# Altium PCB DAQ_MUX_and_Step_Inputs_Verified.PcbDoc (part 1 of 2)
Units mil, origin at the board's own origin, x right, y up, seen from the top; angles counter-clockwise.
Board outline 3200 x 1700 mil, 4 copper layers (Top Layer, InternalPlane1, InternalPlane2, Bottom Layer), stack 61.7 mil thick; 78 components, 60 nets, 284 pads, 100 vias.
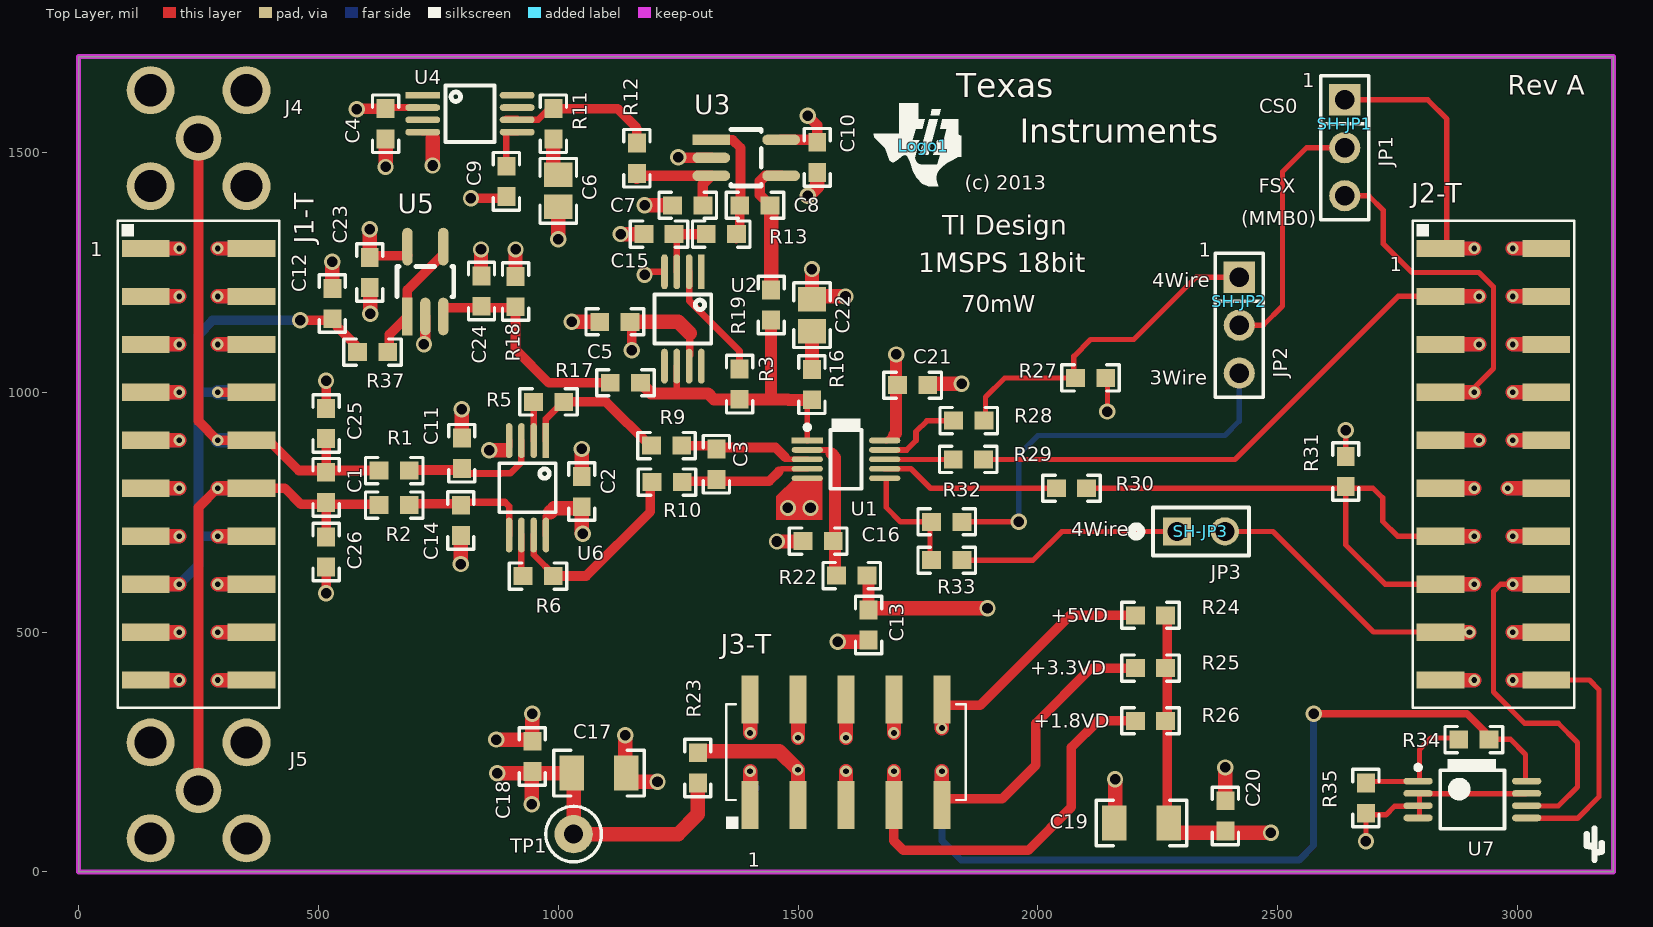
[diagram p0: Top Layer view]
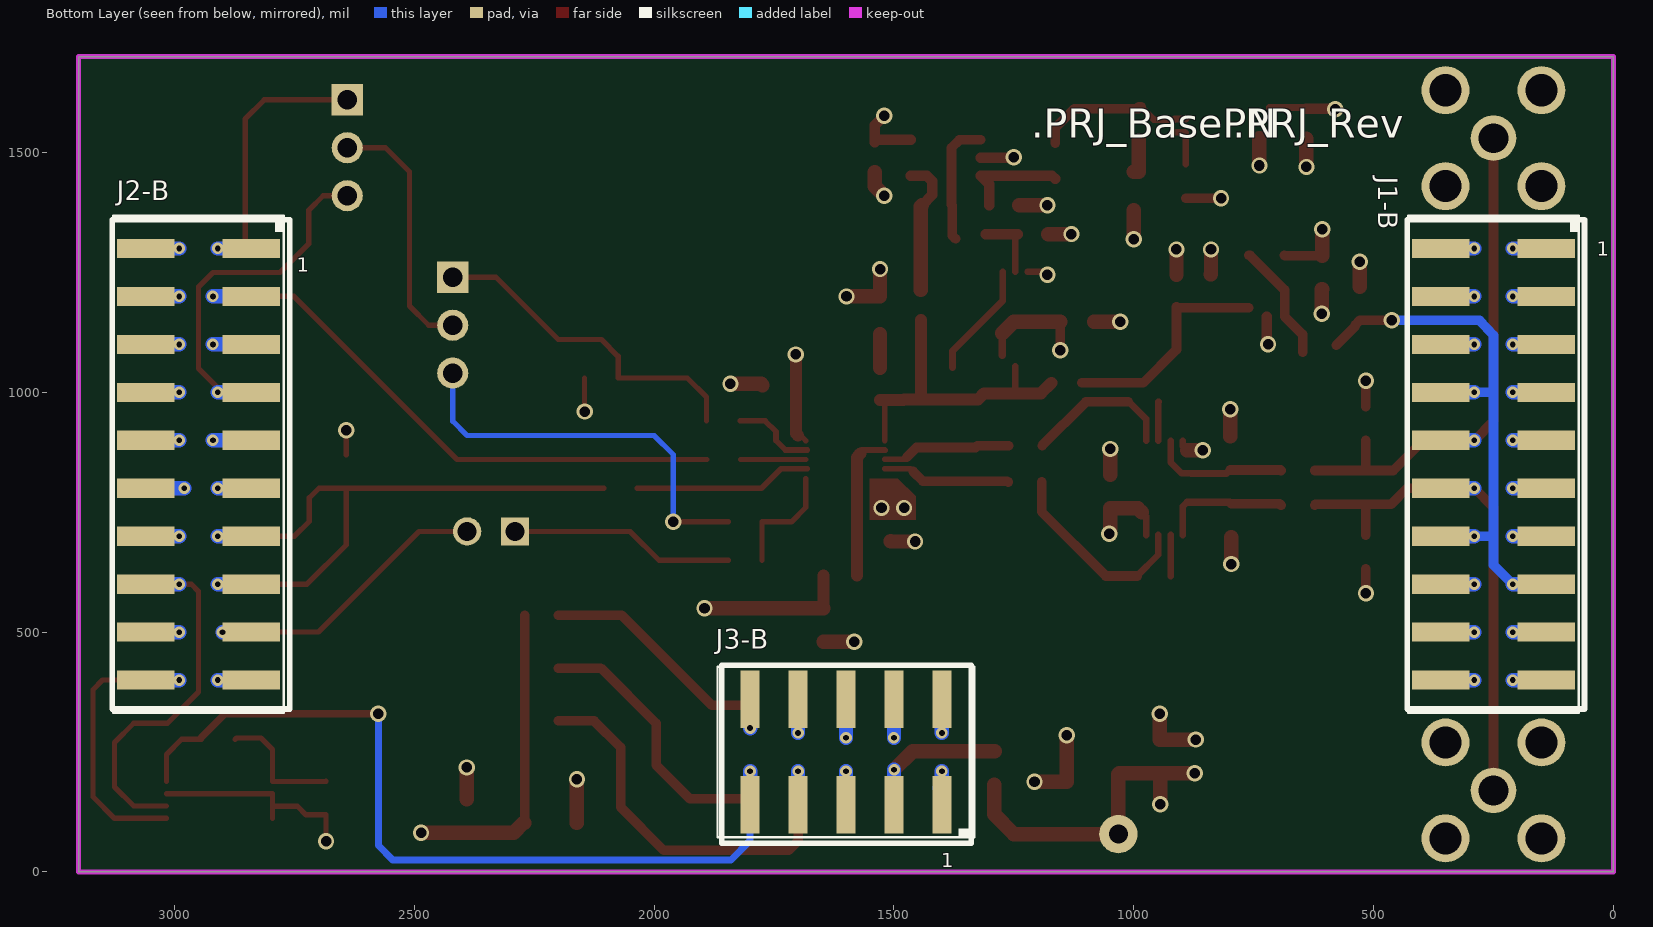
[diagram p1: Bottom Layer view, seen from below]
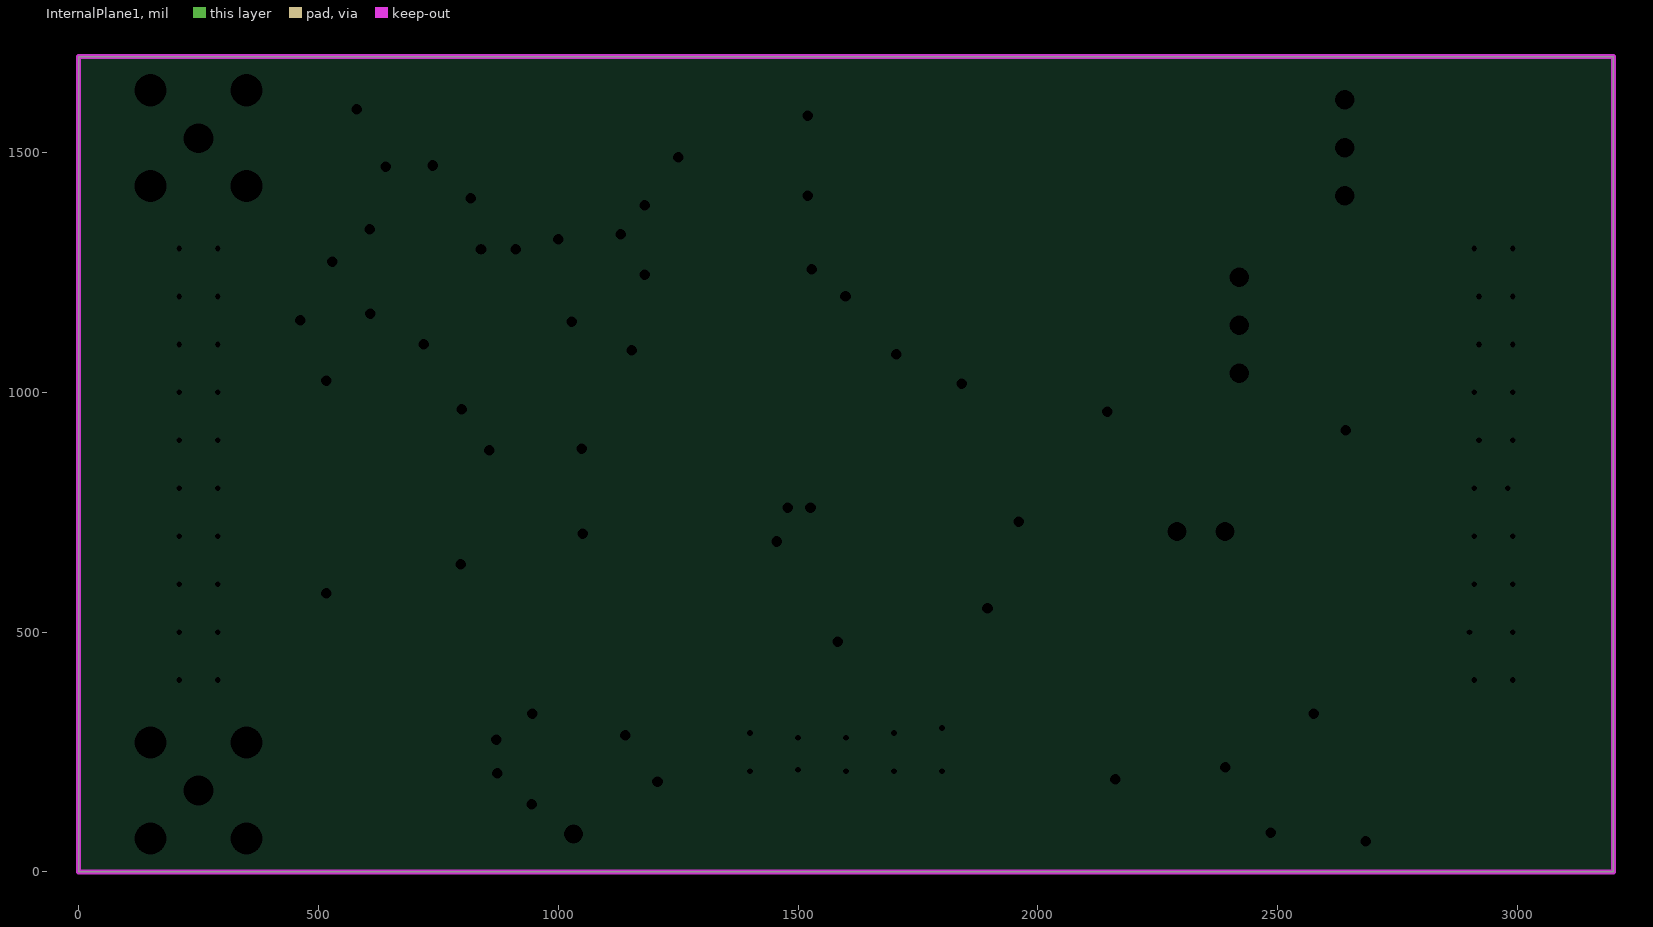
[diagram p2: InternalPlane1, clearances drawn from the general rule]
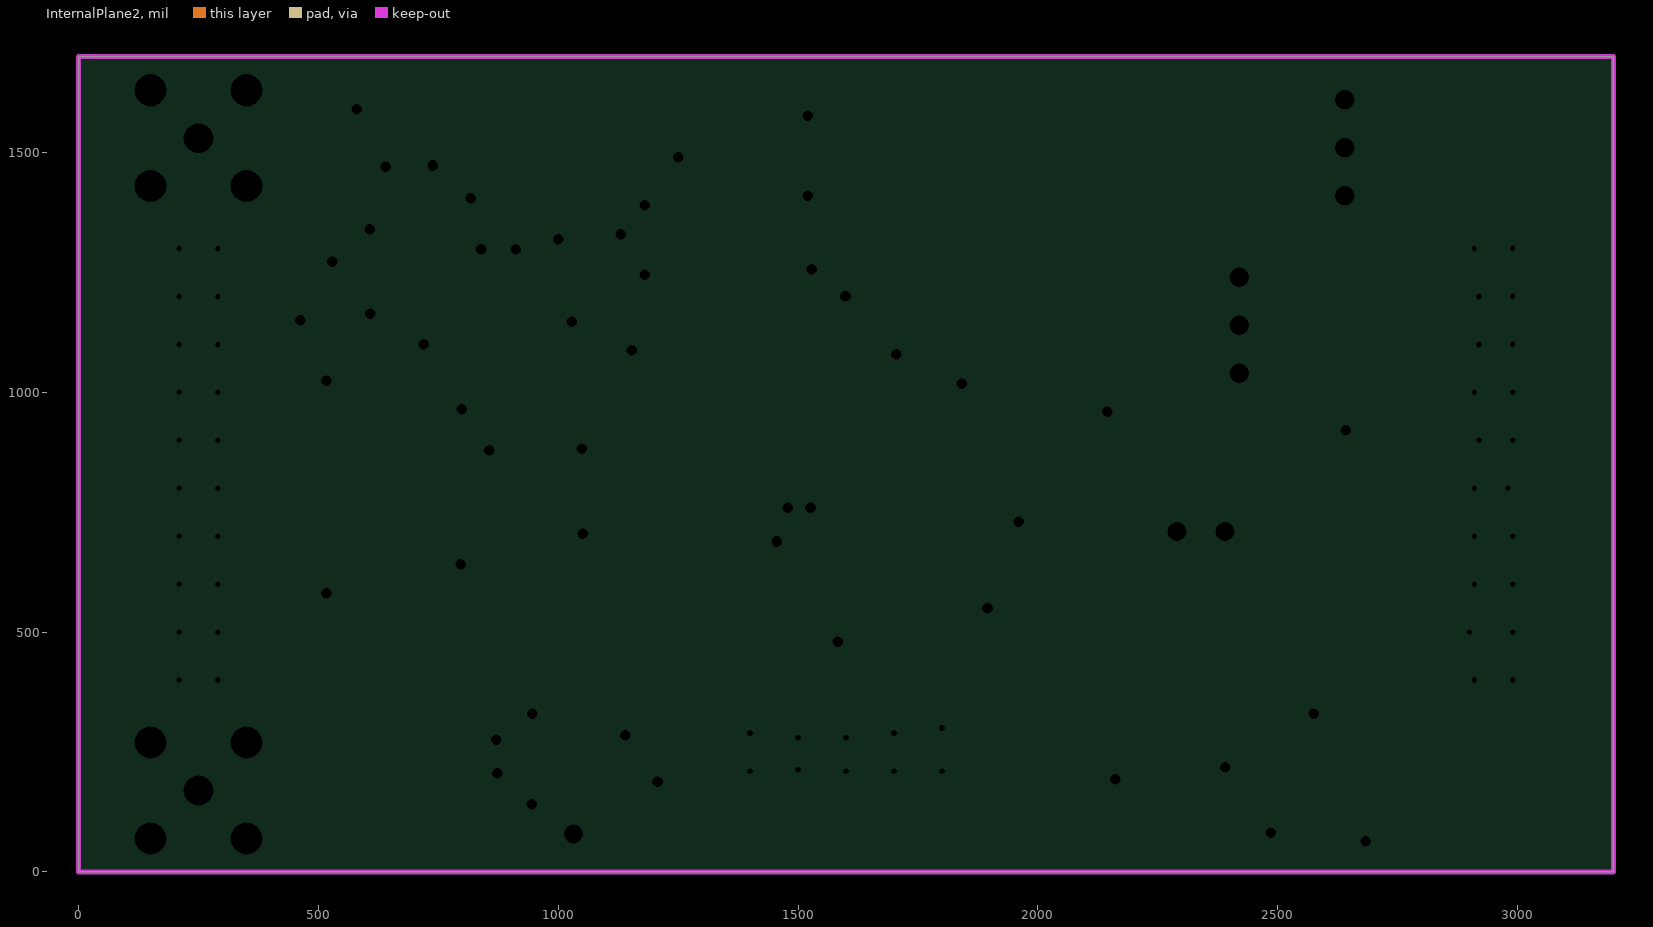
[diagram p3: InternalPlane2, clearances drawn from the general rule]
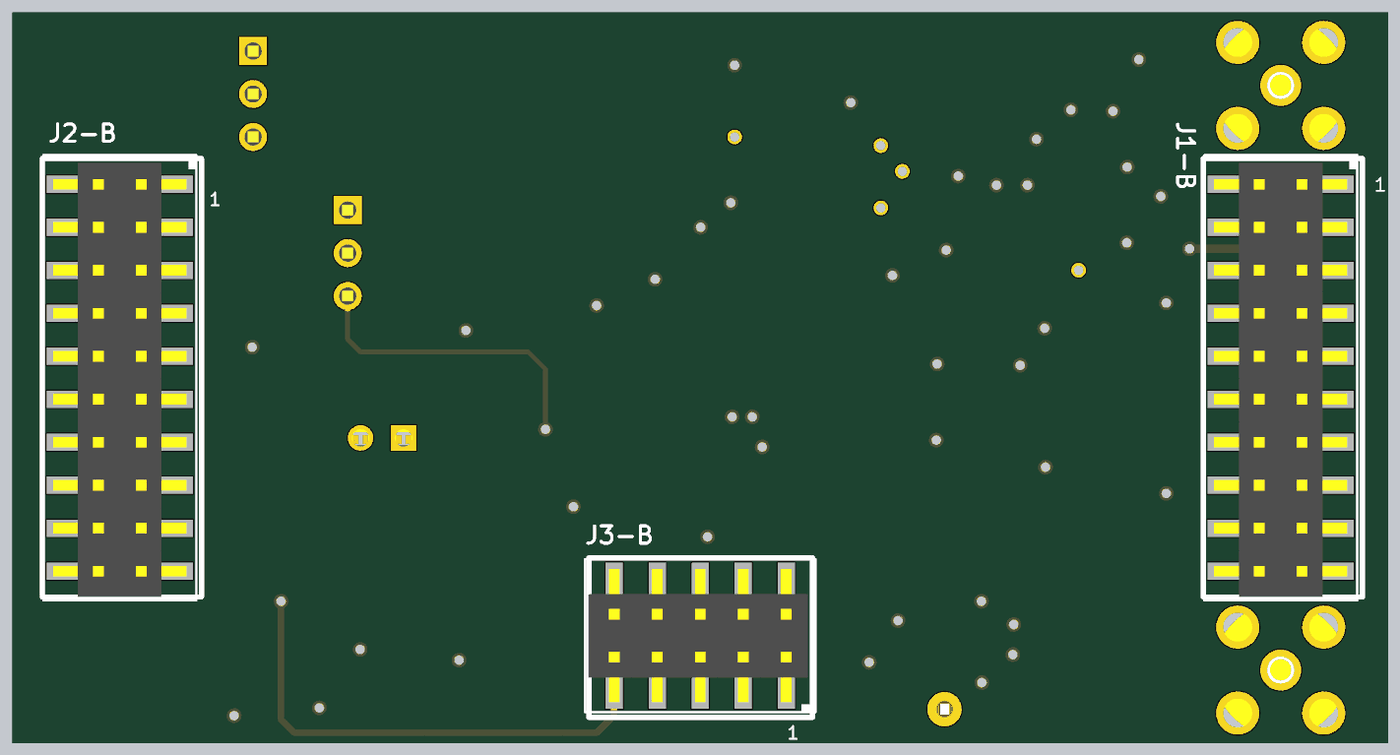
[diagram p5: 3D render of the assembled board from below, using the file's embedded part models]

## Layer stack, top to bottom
Top Layer: signal copper 1.4
Dielectric: core 12.6, FR-4, Dk 4.8
InternalPlane1: plane copper 1.4, net AGND
Dielectric: prepreg 30.9, FR-4, Dk 4.8
InternalPlane2: plane copper 1.4, net (Multiple Nets)
Dielectric: core 12.6, FR-4, Dk 4.8
Bottom Layer: signal copper 1.4

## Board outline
0,0 3200,0 3200,1700 0,1700

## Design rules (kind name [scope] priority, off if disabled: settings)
AcuteAngle [All] p1: minimum=4.50000000000000E+0001 checktracksonly=FALSE
AssemblyTestPointUsage [All] p1: valid=2
Clearance Clearance_BoardEdge_MountingHoles [OnCopper and InComponentClass('Mounting Holes') vs IsKeepOut] p1: gap=40
Clearance Clearance_BoardEdge_Poly [OnCopper and InPoly vs IsKeepOut] p2: gap=25
Clearance Clearance_BoardEdge [OnCopper and Not InComponentClass('Logo') and not InComponentClass('FiducialMark') and not InRegion(1000,500,4000,800) vs IsKeepOut] p3: gap=10
Clearance [All] p4: gap=7.87
ComponentClearance ComponentClearance_Shunts [InComponentClass('Shunt')] p1: gap=0 collisioncheckmode=3 verticalgap=0 showdistances=FALSE
ComponentClearance ComponentClearance_Jumpers [HasFootprint('TSW-102-07-G-S') or HasFootprint('TSW-103-07-G-S')] p2: gap=20 collisioncheckmode=3 verticalgap=10 showdistances=FALSE
ComponentClearance ComponentClearance_Logo [InComponentClass(Logo)] p3: gap=50 collisioncheckmode=3 verticalgap=10 showdistances=FALSE
ComponentClearance ComponentClearance_ScrewToNut [(HasFootprint('NY PMS 440 0025 PH')) vs (HasFootprint('Keystone_1902C'))] p4: gap=5 collisioncheckmode=3 verticalgap=10 showdistances=FALSE
ComponentClearance ComponentClearance_MountingHoles [InComponentClass('Mounting Holes')] p5: gap=250 collisioncheckmode=3 verticalgap=100000 showdistances=FALSE
ComponentClearance ComponentClearance_SmallPassives [HasFootprint('0201*') or HasFootprint('0402*') or HasFootprint('0508') or HasFootprint('0603*') or HasFootprint('0612') or HasFootprint('0805*') or HasFootprint('0815*') or HasFootprint('0830*') or HasFootprint('1206*') or HasFootprint('1210*') or HasFootprint('1808*') or HasFootprint('1812*') or HasFootprint('1825*') or HasFootprint('2010*') or HasFootprint('2220*') or HasFootprint('2225*') or HasFootprint('2512*') or HasFootprint('2728*') or HasFootprint('3518*') vs HasFootprint('0201*') or HasFootprint('0402*') or HasFootprint('0508') or HasFootprint('0603*') or HasFootprint('0612') or HasFootprint('0805*') or HasFootprint('0815*') or HasFootprint('0830*') or HasFootprint('1206*') or HasFootprint('1210*') or HasFootprint('1808*') or HasFootprint('1812*') or HasFootprint('1825*') or HasFootprint('2010*') or HasFootprint('2220*') or HasFootprint('2225*') or HasFootprint('2512*') or HasFootprint('2728*') or HasFootprint('3518*')] p6: gap=15 collisioncheckmode=3 verticalgap=10 showdistances=FALSE
ComponentClearance ComponentClearance_THtoSMT [IsThruComponent vs IsSMTComponent] p7: gap=7 collisioncheckmode=3 verticalgap=100000 showdistances=TRUE
ComponentClearance ComponentClearance_THtoTH [IsThruComponent vs IsThruComponent] p8: gap=5 collisioncheckmode=3 verticalgap=100000 showdistances=FALSE
ComponentClearance [All] p9 off: gap=40 collisioncheckmode=3 verticalgap=10 showdistances=FALSE
DiffPairsRouting [All] p1: maxlimit=100 minlimit=10 mostfreqgap=10 maxuncoupledlength=1000
FabricationTestPointUsage TestPointUsage [All] p1: valid=2 allowmultiple=FALSE
FabricationTestpoint Testpoint [All] p1: side=3 testpointundercomponent=TRUE minsize=40 maxsize=100 preferedsize=60 minholesize=0 maxholesize=40 preferedholesize=32 testpointgrid=1 allowsidetop=TRUE allowsidebottom=TRUE usegrid=TRUE gridtolerance=0.01
FanoutControl Fanout_LCC [IsLCC] p1: bgadir=Out bgaviamode=Centered fanoutstyle=Auto fanoutdirection=Alternating viagrid=1 // Fanout_LCC (Default Rule)
FanoutControl Fanout_BGA [IsBGA] p2: bgadir=Out bgaviamode=Centered fanoutstyle=Auto fanoutdirection=Alternating viagrid=1 // Fanout_BGA (Default Rule)
FanoutControl Fanout_Default [All] p4: bgadir=Out bgaviamode=Centered fanoutstyle=Auto fanoutdirection=Alternating viagrid=1 // Fanout_Default (Default Rule)
FanoutControl Fanout_Small [(CompPinCount < 5)] p5: bgadir=Out bgaviamode=Centered fanoutstyle=Auto fanoutdirection=OutThenIn viagrid=1 // Fanout_Small (Default Rule)
HoleSize [All] p1: absolutevalues=TRUE maxlimit=251 minlimit=8 maxpercent=80.000 minpercent=20.000
MinimumAnnularRing [All] p1: minimumring=4
MinimumSolderMaskSliver MinimumSolderMaskSliver_Logo [InComponentClass('Logo') vs InComponentClass('Logo')] p1: minsoldermaskwidth=0.7
MinimumSolderMaskSliver [All] p2: minsoldermaskwidth=3.8
PlaneClearance [All] p1: clearance=20
PlaneConnect PlaneConnect_VIAS [IsVia] p1: planeconnectstyle=Direct reliefexpansion=20 reliefentries=4 reliefconductorwidth=10 reliefairgap=10
PlaneConnect [All] p2: planeconnectstyle=Relief reliefexpansion=10 reliefentries=4 reliefconductorwidth=20 reliefairgap=10
PolygonConnect [All] p1: connectstyle=Relief reliefconductorwidth=20 reliefentries=4 polygonreliefangle="45 Angle" airgapwidth=10
RoutingVias [All] p1: holewidth=22 width=34 viastyle="Through Hole" minholewidth=8 minwidth=15 maxholewidth=22 maxwidth=34
SMDToCorner [All] p1: distance=15000
SilkToSilkClearance [All] p1: silktosilkclearance=1.5
SilkscreenOverComponentPads [All] p1: minsilkscreentomaskgap=4
SolderMaskExpansion [All] p1: expansion=3
Width [All] p1: maxlimit=100 minlimit=6 preferedwidth=13.78 checkconnectedcopper=TRUE
13 further rules are at their usual default settings.

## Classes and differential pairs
component class Shunt: SH-JP1 SH-JP2 SH-JP3
component class Logo: Logo1
component class Header: JP1 JP2

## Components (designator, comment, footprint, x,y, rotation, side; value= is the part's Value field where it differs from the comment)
C1 "N/A" 0603 516,802 r90 top
C2 "06033C104KAT2A" 0603 1049,793 r90 top
C3 "C0603C102J5GAC" 0603 1330,850 r90 top
C4 "GRM188R71A105KA61D" 0603 640,1560 r90 top
C5 "06033C104KAT2A" 0603 1118,1147 r180 top
C6 "GRM21BR71A106KE51L" 0805 1000,1420 r270 top
C7 "GRM188R71A105KA61D" 0603 1270,1390 r0 top
C8 "GRM188R71A105KA61D" 0603 1410,1390 r180 top
C9 "GRM188R71A105KA61D" 0603 892,1440 r90 top
C10 "06033C104KAT2A" 0603 1540,1490 r270 top
C11 "N/A" 0603 799,873 r270 top
C12 "GRM188R71A105KA61D" 0603 529,1185 r270 top
C13 "GRM188R71A105KA61D" 0603 1647,515 r90 top
C14 "N/A" 0603 797,733 r90 top
C15 "GRM188R71A105KA61D" 0603 1210,1330 r0 top
C16 "C0603C102J5GAC" 0603 1542,690 r0 top
C17 "GRM31CR71C106KAC7L" 1206 1085,206 r0 top
C18 "C0603C102J5GAC" 0603 946,241 r270 top
C19 "GRM31CR71C106KAC7L" 1206 2216,102 r180 top
C20 "C0603C102J5GAC" 0603 2391,117 r270 top
C21 "GRM188R71A105KA61D" 0603 1739,1015 r180 top
C22 "GRM21BR71A106KE51L" 0805 1529,1161 r90 top
C23 "06033C104KAT2A" 0603 607,1250 r270 top
C24 "GRM188R71A105KA61D" 0603 840,1211 r270 top
C25 "N/A" 0603 516,935 r270 top
C26 "N/A" 0603 516,667 r90 top
J1-B "Bottom Side Connector" CONN_SSW-110-22-F-D-VS-K 250,850 r90 bottom
J1-T "TSM-110-01-T-DV-P" CONN_TSM-110-01-T-DV-P 250,850 r270 top
J2-B "Bottom Side Connector" CONN_SSW-110-22-F-D-VS-K 2950,850 r90 bottom
J2-T "TSM-110-01-T-DV-P" CONN_TSM-110-01-T-DV-P 2950,850 r270 top
J3-B "SSW-105-22-F-D-VS-K" CONN_SSW-105-22-F-D-VS-K 1600,250 r180 bottom
J3-T "TSM-105-01-T-DV-P" CONN_TSM-105-01-T-DV-P 1600,250 r0 top
J4 "142-0701-201" Johnson_142-0701-20x 250,1530 r0 top
J5 "142-0701-201" Johnson_142-0701-20x 250,170 r0 top
JP1 "PBC03SAAN" PBC03SAAN 2640,1510 r270 top
JP2 "PBC03SAAN" PBC03SAAN 2420,1140 r270 top
JP3 "5-146261-1" CONN_5-146261-1 2340,710 r0 top
Logo1 "Texas Instruments" TIBUG2-NEW 1761,1514 r0 top
R1 "RC0603FR-0747RL" 0603 658,837 r180 top
R2 "RC0603FR-0747RL" 0603 658,765 r180 top
R3 "ERJ-3GEY0R00V" 0603 1378,1017 r270 top
R5 "ERJ-3GEY0R00V" 0603 980,980 r0 top
R6 "ERJ-3GEY0R00V" 0603 958,617 r0 top
R9 "CRCW060310R0FKEA" 0603 1226,889 r0 top
R10 "CRCW060310R0FKEA" 0603 1227,813 r0 top
R11 "ERJ-3RQFR22V" 0603 990,1560 r270 top
R12 "CRCW06031K00FKEA" 0603 1164,1488 r270 top
R13 "CRCW06031K00FKEA" 0603 1340,1330 r180 top
R16 "ERJ-3RQFR22V" 0603 1529,1016 r90 top
R17 "CRCW060320K0FKEA" 0603 1140,1020 r0 top
R18 "CRCW060320K0FKEA" 0603 911,1210 r90 top
R19 "CRCW060320K0FKEA" 0603 1444,1182 r270 top
R22 "CRCW060310R0FKEA" 0603 1612,618 r180 top
R23 "ERJ-3GEY0R00V" 0603 1291,217 r90 top
R24 "Uninstalled" 0603 2235,535 r0 top
R25 "ERJ-3GEY0R00V" 0603 2235,425 r0 top
R26 "Uninstalled" 0603 2235,315 r0 top
R27 "CRCW060320K0FKEA" 0603 2110,1030 r180 top
R28 "RC0603FR-0747RL" 0603 1856,941 r0 top
R29 "RC0603FR-0747RL" 0603 1855,860 r0 top
R30 "ERJ-3GEY0R00V" 0603 2070,800 r0 top
R31 "CRCW060320K0FKEA" 0603 2642,835 r270 top
R32 "RC0603FR-0747RL" 0603 1810,730 r0 top
R33 "RC0603FR-0747RL" 0603 1810,650 r0 top
R34 "Uninstalled" 0603 2909,276 r0 top
R35 "RC0603FR-0747RL" 0603 2684,154 r270 top
R37 "CRCW06031K00FKEA" 0603 613,1084 r180 top
SH-JP1 "969102-0000-DA" SNT-100-BK-G 2640,1560 r90 top
SH-JP2 "969102-0000-DA" SNT-100-BK-G 2420,1190 r90 top
SH-JP3 "969102-0000-DA" SNT-100-BK-G 2340,710 r0 top
TP1 "5000" Keystone5000 1032,79 r0 top
U1 "ADS8881IDGS" DGS-10 1600,860.25 r0 top
U2 "THS4281DGK" DGK-8 1260,1153 r270 top
U3 "OPA333AIDBVT" DBV-5 1392,1489 r0 top
U4 "REF5045AIDGKT" DGK-8 816,1581 r0 top
U5 "OPA333AIDBVT" DBV-5 723,1231 r90 top
U6 "OPA2350EA/250" DGK-8 936,801 r270 top
U7 "24LC256-I/ST" TSSOP-8 2906,151 r0 top

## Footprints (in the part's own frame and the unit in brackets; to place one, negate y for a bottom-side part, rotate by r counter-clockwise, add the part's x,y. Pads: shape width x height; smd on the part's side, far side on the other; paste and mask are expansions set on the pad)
0603 [mm] "0603 from SM-752 data"
  rect 1x0.95 smd: 1(-0.8,0) 2(0.8,0)
  silkscreen extent -1.52,-0.69 1.52,0.69, body extent -0.87,-0.47 0.87,0.47, height 0.85
0805 [mm] "0805 from SM-752 data"
  rect 1.3x1.5 smd: 1(-0.85,0) 2(0.85,0)
  silkscreen extent -1.72,-0.97 1.72,0.97, body extent -1.1,-0.72 1.1,0.72, height 1.1
1206 [mm] "1206 from SM-752 data"
  rect 1.3x1.85 smd: 1(-1.45,0) 2(1.45,0)
  silkscreen extent -2.4,-1.21 2.4,1.21, body extent -1.7,-0.9 1.7,0.9, height 1.35
CONN_5-146261-1 [mm] "Sullins"
  rect 1.5x1.5 hole 1.02: 1(-1.27,0)
  round 1.5 hole 1.02: 2(1.27,0)
  silkscreen extent -3.68,-1.27 2.54,1.27, body extent -2.51,-1.27 2.51,1.27, height 10.87
CONN_SSW-105-22-F-D-VS-K [mil]
  rect 40x120 smd: 1(200,-110) 2(200,110) 3(100,-110) 4(100,110) 5(0,-110) 6(0,110) 7(-100,-110) 8(-100,110) 9(-200,-110) 10(-200,110)
  silkscreen extent -268,-178 268,178, body extent -260,-155 250,155, height 435
CONN_SSW-110-22-F-D-VS-K [mil]
  rect 40x120 smd: 1(450,-110) 2(450,110) 3(350,-110) 4(350,110) 5(250,-110) 6(250,110) 7(150,-110) 8(150,110) 9(50,-110) 10(50,110) 11(-50,-110) 12(-50,110) 13(-150,-110) 14(-150,110) 15(-250,-110) 16(-250,110) 17(-350,-110) 18(-350,110) 19(-450,-110) 20(-450,110)
  silkscreen extent -518,-178 518,178, body extent -510,-155 500,155, height 435
CONN_TSM-105-01-T-DV-P [mil]
  rect 36x100 smd mask+2: 1(-200,-110) 2(-200,110) 3(-100,-110) 4(-100,110) 5(0,-110) 6(0,110) 7(100,-110) 8(100,110) 9(200,-110) 10(200,110)
  silkscreen extent -250,-160 250,100, body extent -250,-145 250,145, height 380
CONN_TSM-110-01-T-DV-P [mil]
  rect 36x100 smd mask+2: 1(-450,-110) 2(-450,110) 3(-350,-110) 4(-350,110) 5(-250,-110) 6(-250,110) 7(-150,-110) 8(-150,110) 9(-50,-110) 10(-50,110) 11(50,-110) 12(50,110) 13(150,-110) 14(150,110) 15(250,-110) 16(250,110) 17(350,-110) 18(350,110) 19(450,-110) 20(450,110)
  silkscreen extent -508,-168 508,168, body extent -500,-145 500,145, height 380
DBV-5 [mm] "PSOP-5 in Custom Library"
  rect 2x0.55 smd: 1(-1.85,0.95)
  oval 2x0.55 smd: 2(-1.85,0) 3(-1.85,-0.95) 4(1.85,-0.95) 5(1.85,0.95)
  silkscreen extent -0.8,-1.5 0.8,1.5, body extent -0.8,-1.52 0.8,1.52, height 1.45
DGK-8 [mm] "SOIC"
  rect 1.85x0.35 smd: 1(-2.5,0.975)
  oval 1.85x0.35 smd: 2(-2.5,0.325) 3(-2.5,-0.325) 4(-2.5,-0.975) 5(2.5,-0.975) 6(2.5,-0.325) 7(2.5,0.325) 8(2.5,0.975)
  silkscreen extent -1.3,-1.5 1.3,1.5, body extent -1.5,-1.5 1.5,1.5, height 1.1
DGS-10 [mm] "TSSOP, 10-Leads, Body 3.1x3.1mm (max), Pitch 0.50mm, IPC Medium Density"
  rect 1.65x0.3 smd: 1(-2.05,1)
  oval 1.65x0.3 smd: 2(-2.05,0.5) 3(-2.05,0) 4(-2.05,-0.5) 5(-2.05,-1) 6(2.05,-1) 7(2.05,-0.5) 8(2.05,0) 9(2.05,0.5) 10(2.05,1)
  silkscreen extent -2.17,-1.55 0.82,1.82, body extent -1.55,-1.55 1.55,1.55, height 1.1
Johnson_142-0701-20x [mil] "Johnson Components recommended land pattern"
  round 95 hole 62: 1(0,0)
  round 100 hole 67: 2(100,100) 3(100,-100) 4(-100,-100) 5(-100,100)
  body extent -156,-156 156,156, height 375
Keystone5000 [mil] "For Keystone 500x miniature loop terminals"
  round 80 hole 40: 1(0,0)
  silkscreen extent -58,-58 58,58, body extent -49,-49 49,49, height 182
PBC03SAAN [mm] "Sullins 100mil, 1x3, 230 mil above insulator"
  rect 1.65x1.65 hole 1.016: 1(-2.54,0)
  round 1.65 hole 1.016: 2(0,0) 3(2.54,0)
  silkscreen extent -3.81,-1.27 3.81,1.27, body extent -3.81,-1.27 3.81,1.27, height 8.38
SNT-100-BK-G [mil] "Samtec STEP model"
  round 1 on Mech3: 0(0,0)
  body extent -100,-50 100,50, height 344
TIBUG2-NEW [mil]
  silkscreen extent -103,-84 79,89
TSSOP-8 [mm] "TSOP, 8-Leads, Body 3.1x4.5mm (max), Pitch 0.65mm, IPC Medium Density"
  oval 1.55x0.35 smd: 1(-2.875,0.975) 2(-2.875,0.325) 3(-2.875,-0.325) 4(-2.875,-0.975) 5(2.875,-0.975) 6(2.875,-0.325) 7(2.875,0.325) 8(2.875,0.975)
  silkscreen extent -3,-1.55 1.7,1.82, body extent -2.25,-1.55 2.25,1.55, height 1.2

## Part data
C1 C11 C14 C25 C26: library part 06033C104KAT2A, "Uninstalled"
C2 C5 C10 C23: "CAP, CERM, 0.1uF, 25V, +/-10%, X7R, 0603"
C3 C16 C18 C20: "CAP, CERM, 1000pF, 50V, +/-5%, C0G/NP0, 0603"
C4 C7 C8 C9 C12 C13 C15 C21 C24: "CAP, CERM, 1uF, 10V, +/-10%, X7R, 0603"
C6 C22: "CAP, CERM, 10uF, 10V, +/-10%, X7R, 0805"
C17 C19: "CAP, CERM, 10uF, 16V, +/-10%, X7R, 1206"
J1-B J2-B: library part SSW-110-22-F-D-VS-K, "Connector, Receptacle, 100mil, 10x2, Gold plated, SMD"
J1-T J2-T: "Header, 100mil, 10x2, SMD"
J3-B: "Connector, Header, 10-Pos (10x2), Receptacle, 100x100-mil Pitch"
J3-T: "Header, 100mil, 5x2, SMD"
J4 J5: "Connector, TH, SMA"
JP1 JP2: "Header, TH, 100mil, 1x3, Gold plated, 230 mil above insulator"
JP3: "Header, 100mil, 2x1, Gold plated, TH"
Logo1: library part TI_Logo, "Texas Instrument Corporate Signature"
R1 R2 R28 R29 R32 R33 R35: "RES, 47.0 ohm, 1%, 0.1W, 0603"
R3 R5 R6 R23 R25 R30: "RES, 0 ohm, 5%, 0.1W, 0603"
R9 R10 R22: "RES, 10.0 ohm, 1%, 0.1W, 0603"
R11 R16: "RES, 0.22 ohm, 1%, 0.1W, 0603"
R12 R13 R37: "RES, 1.00k ohm, 1%, 0.1W, 0603"
R17 R18 R19 R27 R31: "RES, 20.0k ohm, 1%, 0.1W, 0603"
R24 R26 R34: library part ERJ-3GEY0R00V
SH-JP1 SH-JP2 SH-JP3: "Shunt, 100mil, Gold plated, Black"
TP1: "Test Point, Miniature, Red, TH"
U1: "ADC 1MSPS 18bit Fully-Diff MSOP-10"
U2: "IC OpAmp GP R-R 90MHz SGL MSOP-8"
U3 U5: "OpAmp, Low Power, Low Drift, 1.8V"
U4: library part REF5045IDGK, "VREF PREC 4.5V MSOP-8"
U6: library part OPA2350EA

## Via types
v1: diameter 24, hole 12, Top Layer to Bottom Layer, tented both sides, 50 vias
v2: diameter 34/34 (per signal layer), hole 22, Top Layer to Bottom Layer, 47 vias
v3: diameter 34, hole 22, Top Layer to Bottom Layer, 3 vias

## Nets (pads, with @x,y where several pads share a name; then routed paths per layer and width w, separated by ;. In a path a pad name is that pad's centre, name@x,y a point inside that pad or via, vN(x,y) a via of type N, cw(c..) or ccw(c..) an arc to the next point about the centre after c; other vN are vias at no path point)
+1.8VD: J3-B.7 J3-T.7 R26.1 | length 908.4
  Top Layer w20: J3-T.7@1699.9,140 1699.9,65 1719.9,45 1980,45 2070,135 2070,260 2125,315 R26.1@2200,315
  Top Layer w30: J3-T.7@1700,140 v1(1700,210)
  Bottom Layer w30: J3-B.7@1700,140 v1(1700,210)
+3.3VD: J3-B.9 J3-T.9 R25.1 R34.2 U7.8 | length 2409.3
  Top Layer w11: R34.2@2944,281 2944,276 2944.9,276.9 2985,276.9 3016.9,245 U7.8@3016.9,188.6
  Top Layer w15: v2(2575,330) 2895,330 R34.2@2944,281
  Top Layer w20: J3-T.9@1801.22,152.8 1926,152.8 1996,222.8 1996,310 2111,425 R25.1@2200,425
  Top Layer w30: v1(1800,210) J3-T.9@1800,140 1800,139.08 J3-T.9@1801.22,137.86
  Bottom Layer w15: J3-B.9@1799.9,152.8 1799.9,65 1839.9,25 2545,25 2575,55 v2(2575,330)
  Bottom Layer w30: J3-B.9@1800,140 v1(1800,210)
+5VA: J3-B.3 J3-T.3 R23.2 | length 372.3
  Top Layer w30: R23.2@1290,252 1461,252 v1(1499.9,213.1) 1500,213 J3-T.3@1500,140
  Bottom Layer w30: v1(1499.9,213.1) 1500,213 J3-B.3@1500,140
+5VD: J3-B.10 J3-T.10 R24.1 | length 597.6
  Top Layer w20: J3-T.10@1799.9,347.8 1800,347.8 1880,347.8 2067.2,535 R24.1@2200,535
  Top Layer w30: v1(1800,300) 1800,347.8 J3-T.10@1800,360
  Bottom Layer w30: v1(1800,300) J3-B.10@1800,360
A0(+): C1.2 C25.2 J1-B.10 J1-T.10 J4.1 R1.2 | length 1102.7
  Top Layer w20: J4.1@250,1530 250,940 v1(290,900) J1-T.10@360,900 ; J1-T.10@396,900.1 459,837.1 515.9,837.1 C1.2@516,837 ; C25.2@516,900 C1.2@516,837 ; R1.2@623,837 C1.2@516,837
  Bottom Layer w30: v1(290,900) J1-B.10@360,900
A0(-): C1.1 C26.2 J1-B.12 J1-T.12 J5.1 R2.2 | length 1129.1
  Top Layer w20: J5.1@250,170 250,760 v1(290,800) ; J1-T.12@360,800.1 429.9,800.1 463,767 C1.1@516,767 ; C26.2@516,702 C1.1@516,767 ; R2.2@623,765 621,767 C1.1@516,767
  Top Layer w30: v1(290,800) J1-T.12@360,800
  Bottom Layer w30: v1(290,800) J1-B.12@360,800
AGND: C2.2 C4.1 C5.2 C6.2 C7.1 C9.1 C10.2 C11.1 C12.1 C13.1 C14.1 C15.1 C16.1 C17.2 C18.1 C19.2 C20.1 C21.1 C22.2 C23.2 C24.1 C25.1 C26.1 J1-B.1 J1-B.2 J1-B.3 J1-B.4 J1-B.5 J1-B.6 J1-B.7 J1-B.9 J1-B.11 J1-B.13 J1-B.16 J1-B.17 J1-B.18 J1-B.19 J1-B.20 J1-T.1 J1-T.2 J1-T.3 J1-T.4 J1-T.5 J1-T.6 J1-T.7 J1-T.9 J1-T.11 J1-T.13 J1-T.16 J1-T.17 J1-T.18 J1-T.19 J1-T.20 J2-B.4 J2-B.10 J2-B.18 J2-T.4 J2-T.10 J2-T.18 J3-B.5 J3-B.6 J3-T.5 J3-T.6 J4.2 J4.3 J4.4 J4.5 J5.2 J5.3 J5.4 J5.5 R18.2 R35.2 U1.5 U2.4 U3.2 U4.4 U5.2 U6.4 U7.2 U7.3 U7.4 U7.7 | length 5205.2
  Top Layer w11: v2(2684,64) 2684,119 2726,119 2744,137 2795.5,137 U7.3@2795.9,137.4 ; U7.4@2795.9,111.8 U7.3@2795.9,137.4 ; U7.7@3016.9,163 2795.9,163 U7.3@2795.9,137.4
  Top Layer w12.99: v3(1180,1245) 1186.43,1251.43 U2.4@1221.61,1251.43
  Top Layer w13.78: U4.4@717.57,1542.61 725.39,1542.61 738,1530 ; 889,879 897.61,887.61 U6.4@897.61,899.43
  Top Layer w20: v2(516,581) C26.1@516,632 ; C25.1@516,970 v2(516,1024) ; v2(818,1405) C9.1@892,1405
  Top Layer w21.65: v2(720,1100) 723,1103 U5.2@723,1158.17 ; v2(1250,1490) 1251,1489 U3.2@1319.17,1489
  Top Layer w30: J1-T.3@130,1200 v1(210,1200) ; J1-T.19@140,400 v1(210,400) ; J1-T.17@140,500 v1(210,500) ; J1-T.13@140,700 v1(210,700) ; J1-T.11@140,800 v1(210,800) ; J1-T.9@140,900 v1(210,900) ; J1-T.1@140,1300 v1(210,1300) ; J1-T.7@150,1000 v1(210,1000) ; J1-T.5@150,1100 v1(210,1100) ; v1(290,400) J1-T.20@360,400 ; v1(290,500) J1-T.18@360,500 ; v1(290,600) J1-T.16@360,600 ; v1(290,1100) J1-T.6@360,1100 ; v1(290,1200) J1-T.4@360,1200 ; v1(290,1300) J1-T.2@360,1300 ; C12.1@529,1220 v2(529,1272) ; C23.2@607,1215 608,1215 v2(608,1164) ; v2@640,1480 C4.1@640,1528.5 ; v2(738,1473) 738,1530 ; v2(797,642) C14.1@797,698 ; C11.1@799,908 v2(799,965) ; v2(839,1298) 839,1246 C24.1@840,1246 ; v2(856,879) 889,879 ; v2(871,276) 946,276 v2(946,330) ; R18.2@911,1245 v2(911,1298) ; v2(1000,1319) C6.2@1000,1380 ; v2(1028,1147) C5.2@1083,1147 ; C2.2@1049,828 v2(1049,882) ; v3(1130,1330) C15.1@1178.5,1330 ; v2(1140,285) 1140,188 v2(1207,188) ; v3(1180,1390) C7.1@1238.5,1390 ; v2(1456,689) 1507,689 C16.1@1507,690 ; v2(1520,1410) 1540,1430 C10.2@1540,1458.5 ; v2(1529,1257) 1529,1200 v2(1599,1200) ; v2(1583,480) C13.1@1647,480 ; J3-T.5@1600,140 v1(1600,210) ; v1(1600,280) J3-T.6@1600,360 ; C21.1@1774,1015 1777,1018 v2(1841,1018) ; C19.2@2161,102 v2(2161,193) ; C20.1@2391,152 v2(2391,218) ; v1(2990,500) J2-T.18@3060,500 ; v1(2990,900) J2-T.10@3060,900 ; v1(2990,1200) J2-T.4@3060,1200
  Bottom Layer w30: J1-B.19@140,400 v1(210,400) ; J1-B.17@140,500 v1(210,500) ; J1-B.13@140,700 v1(210,700) ; J1-B.11@140,800 v1(210,800) ; J1-B.9@140,900 v1(210,900) ; J1-B.7@140,1000 v1(210,1000) ; J1-B.5@140,1100 v1(210,1100) ; J1-B.1@140,1300 v1(210,1300) ; J1-B.3@150,1200 v1(210,1200) ; v1(290,400) J1-B.20@360,400 ; v1(290,500) J1-B.18@360,500 ; v1(290,600) J1-B.16@360,600 ; v1(290,1100) J1-B.6@360,1100 ; v1(290,1200) J1-B.4@360,1200 ; v1(290,1300) J1-B.2@360,1300 ; J3-B.5@1600,140 v1(1600,210) ; v1(1600,280) J3-B.6@1600,360 ; v1(2990,500) J2-B.18@3060,500 ; v1(2990,900) J2-B.10@3060,900 ; v1(2990,1200) J2-B.4@3060,1200
  other v2: 1479,759 1526,759 640,1470
AVDD: C2.1 C4.2 C5.1 C10.1 C17.1 C18.2 C23.1 R23.1 TP1.1 U2.7 U3.5 U4.2 U5.5 U6.8 | length 1514.9
  Top Layer w13.78: C4.2@640,1591.5 642.3,1593.8 U4.2@717.57,1593.8 ; U6.8@974.39,702.57 974.39,741.29 983.1,750
  Top Layer w15: U2.7@1274.4,1077.4 1274.4,1123
  Top Layer w20: C23.1@607,1285 U5.5@685,1285 ; v2(1153,1088) C5.1@1153,1147 ; U5.5@685,1285 685.5,1285 686,1285.5 U5.5@685,1285
  Top Layer w21.65: v2(580,1590) 581.5,1591.5 C4.2@640,1591.5 ; U3.5@1464.83,1526.4 1535.09,1526.4 C10.1@1540,1521.5 1540,1557 v2(1520,1577)
  Top Layer w30: C23.1@607,1285 v2(607,1340) ; v2(873,206) C18.2@946,206 ; v2(945,141) 945,205 C18.2@946,206 ; 983.1,750 991.1,758 1049,758 1049,705 v2(1051,705) ; C5.1@1153,1147 1250.4,1147 1274.4,1123 ; R23.1@1291,182 1291,120 1250,79 TP1.1@1032,79 1032,204 1030,206 C18.2@946,206
CS0: J2-B.1 J2-T.1 JP1.1 | length 639.3
  Top Layer w11: JP1.1@2640,1610 2812.8,1610 2852.8,1570 J2-T.1@2852.8,1300.1
  Top Layer w30: J2-T.1@2840,1300 v1(2910,1300)
  Bottom Layer w30: J2-B.1@2840,1300 v1(2910,1300)
CS0/FSX: JP1.2 JP2.2 | length 537.3
  Top Layer w11: JP2.2@2420,1140 2470,1140 2510,1180 2510,1460 2560,1510 JP1.2@2640,1510
DVDD: C13.2 C19.1 C20.2 C21.2 R22.1 R24.2 R25.2 R26.2 R27.1 R31.1 U1.10 | length 1285.2
  Top Layer w11: U1.10@1684,899.25 1694.75,910 1700,910 ; v2(2145,960) R27.1@2145,1030 ; R31.1@2642,870 v2(2642,921)
  Top Layer w20: R24.2@2270,535 2270,425 2270,315 2270,103 C19.1@2271,102
  Top Layer w25: C13.2@1647,550 R22.1@1647,618 ; 1700,910 1704,914 1704,1015 1704,1078 v2(1705,1079)
  Top Layer w30: C13.2@1647,550 v2(1895,550) ; C19.1@2271,102 2273,102 2293,82 2391,82 v2(2486,82)
FSX: J2-B.7 J2-T.7 JP1.3 | length 803.3
  Top Layer w11: JP1.3@2640,1410 2690,1410 2720,1380 2720,1310 2780,1250 2920,1250 2950,1220 2950,1050.1 v1@2904.95,1005.05
  Top Layer w30: J2-T.7@2840,1000 v1(2910,1000)
  Bottom Layer w30: J2-B.7@2840,1000 v1(2910,1000)
J2-2: J2-B.2 J2-T.2 | length 140
  Top Layer w30: v1(2990,1300) J2-T.2@3060,1300
  Bottom Layer w30: v1(2990,1300) J2-B.2@3060,1300
J2-5: J2-B.5 J2-T.5 | length 160
  Top Layer w30: J2-T.5@2840,1100 2900,1100 2910,1100 v1(2920,1100)
  Bottom Layer w30: J2-B.5@2840,1100 v1(2920,1100)
J2-6: J2-B.6 J2-T.6 | length 140
  Top Layer w30: v1(2990,1100) J2-T.6@3060,1100
  Bottom Layer w30: v1(2990,1100) J2-B.6@3060,1100
J2-8: J2-B.8 J2-T.8 | length 140
  Top Layer w30: v1(2990,1000) J2-T.8@3060,1000
  Bottom Layer w30: v1(2990,1000) J2-B.8@3060,1000
J2-9: J2-B.9 J2-T.9 | length 160
  Top Layer w30: J2-T.9@2840,900 2910,900 v1(2920,900)
  Bottom Layer w30: J2-B.9@2840,900 v1(2920,900)
J2-11: J2-B.11 J2-T.11 | length 130
  Top Layer w30: J2-T.11@2850,800 v1(2910,800)
  Bottom Layer w30: J2-B.11@2840,800 v1(2910,800)
J2-12: J2-B.12 J2-T.12 | length 160
  Top Layer w30: v1(2980,800) 2990,800 J2-T.12@3060,800
  Bottom Layer w30: v1(2980,800) J2-B.12@3060,800
J2-14: J2-B.14 J2-T.14 | length 140
  Top Layer w30: v1(2990,700) J2-T.14@3060,700
  Bottom Layer w30: v1(2990,700) J2-B.14@3060,700
J2-19: J2-B.19 J2-T.19 | length 140
  Top Layer w30: J2-T.19@2840,400 v1(2910,400)
  Bottom Layer w30: J2-B.19@2840,400 v1(2910,400)
J3-1: J3-B.1 J3-T.1 | length 177.2
  Top Layer w30: J3-T.1@1400,140 v1(1400,210)
  Bottom Layer w30: v1(1400,210) J3-B.1@1400,140 1400,170 J3-B.1@1405.13,175.13
J3-2: J3-B.2 J3-T.2 | length 140
  Top Layer w30: v1(1400,290) J3-T.2@1400,360
  Bottom Layer w30: v1(1400,290) J3-B.2@1400,360
J3-4: J3-B.4 J3-T.4 | length 160
  Top Layer w30: v1(1500,280) J3-T.4@1500,360
  Bottom Layer w30: v1(1500,280) J3-B.4@1500,360
J3-8: J3-B.8 J3-T.8 | length 140
  Top Layer w30: v1(1700,290) J3-T.8@1700,360
  Bottom Layer w30: v1(1700,290) 1700,300 J3-B.8@1700,360
NetC3_1: C3.1 R10.2 U1.4 | length 268.7
  Top Layer w11.81: 1460,835 1465.57,840.57 U1.4@1519.29,840.57
  Top Layer w20: R10.2@1262,813 1264,815 1440,815 1460,835
NetC3_2: C3.2 R9.2 U1.3 | length 270.2
  Top Layer w11.81: 1473,865 1477.75,860.25 U1.3@1519.29,860.25
  Top Layer w20: R9.2@1261,889 1326,889 1330,885 1453,885 1473,865
NetC6_1: C6.1 R11.2 | length 75
  Top Layer w30: R11.2@990,1525 990,1460 C6.1@1000,1460
NetC7_2: C7.2 R12.2 U3.3 | length 226.8
  Top Layer w21.65: R12.2@1164,1445 1170.6,1451.6 U3.3@1319.17,1451.6 1301.5,1433.93 C7.2@1301.5,1390
NetC8_1: C8.1 R19.1 U3.4 | length 286.1
  Top Layer w21.65: C8.1@1441.5,1390 1420,1411.5 1420,1440 1431.6,1451.6 U3.4@1464.83,1451.6
  Top Layer w30: C8.1@1441.5,1390 1444,1387.5 R19.1@1444,1213.5
NetC8_2: C8.2 R13.1 U3.1 | length 261.2
  Top Layer w20: U3.1@1319.17,1526.4 1363.6,1526.4 1380,1510 1380,1391.5 C8.2@1378.5,1390 1378.5,1327.01 R13.1@1371.5,1320
NetC9_2: C9.2 U4.5 | length 89.1
  Top Layer w13.78: C9.2@891.6,1475.4 891.6,1541.03 893.19,1542.61 U4.5@914.43,1542.61
NetC11_2: C11.2 R1.1 U6.3 | length 288.1
  Top Layer w13.78: 880,831 900,831 923.2,854.2 U6.3@923.2,899.43
  Top Layer w15: C11.2@799,838 806.8,831 880,831
  Top Layer w20: R1.1@693,837 694,838 C11.2@799,838
NetC14_2: C14.2 R2.1 U6.5 | length 270.6
  Top Layer w13.78: 889.2,771 897.61,762.59 U6.5@897.61,702.57
  Top Layer w15: C14.2@797,768 800,771 889.2,771
  Top Layer w20: R2.1@693,765 696,768 C14.2@797,768
NetC15_2: C15.2 R13.2 U2.3 | length 147.9
  Top Layer w13.78: C15.2@1241.5,1330 1247.2,1324.29 U2.3@1247.2,1251.43
  Top Layer w21.65: C15.2@1241.5,1330 R13.2@1308.5,1330
NetC16_2: C16.2 R22.2 U1.2 | length 314.9
  Top Layer w11: U1.2@1518,879.55 U1.2@1519.29,879.55 ; 1568,879.55 1570,877.55 1570,873 ; C16.2@1577,690 C16.2@1577,696
  Top Layer w11.81: U1.2@1519.29,879.94 1567.61,879.94 1568,879.55
  Top Layer w25: 1570,873 1577,864 C16.2@1577,696 ; R22.2@1577,618 C16.2@1577,690
NetC22_1: C22.1 R16.2 | length 70
  Top Layer w30: R16.2@1529,1051 C22.1@1529,1121
NetC24_2: C24.2 R17.1 R18.1 U5.3 | length 466.8
  Top Layer w20: U5.3@760,1176.5 760.5,1176 R18.1@911,1176 ; R18.1@911,1178.5 R18.1@911,1176 ; R17.1@1108.5,1020 980,1020 911,1089 R18.1@911,1176
NetJP2_1: JP2.1 R27.2 R28.2 | length 707.9
  Top Layer w11: R28.2@1891,941 1891,990 1931,1030 2075,1030 2075,1075 2110,1110 2200,1110 2330,1240 JP2.1@2420,1240
NetJP2_3: JP2.3 R32.2 | length 844
  Top Layer w11: R32.2@1845,730 v2(1960,730)
  Bottom Layer w11: v2(1960,730) 1960,870 2000,910 2390,910 2420,940 JP2.3@2420,1040
NetJP3_1: JP3.1 R33.2 | length 469.9
  Top Layer w11: R33.2@1845,650 1990,650 2050,710 JP3.1@2290,710
NetR3_1: R3.1 U2.2 | length 243
  Top Layer w13.78: U2.2@1272.8,1251.43 1272.8,1191.6 1289.4,1175
  Top Layer w15: 1289.4,1175 1378,1086.4 R3.1@1378,1052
